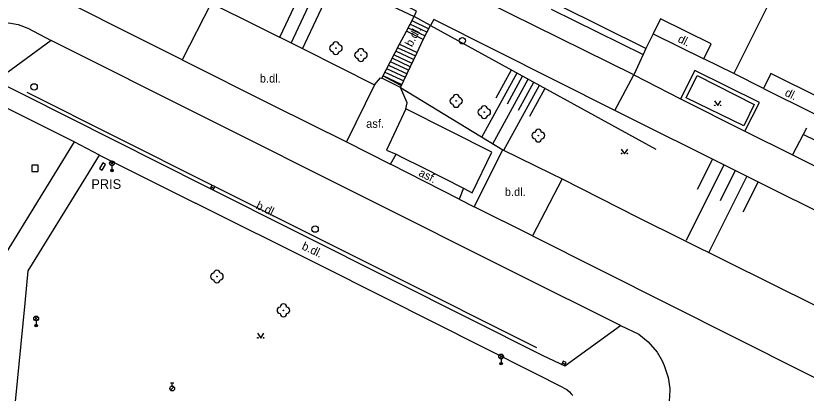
# Model space of a CAD drawing. Extents: x -602419 to -601554, y -1162937 to -1162362.
# Drawn here: x -602170.3 to -602108.3, y -1162597.4 to -1162567.9 of the extents above; entities that cross this region are included whole.
import ezdxf

# ---------------------------------------------------------------- set-up
doc = ezdxf.new("R2010")
doc.units = 0
doc.layers.add('Podklad', color=7, linetype='Continuous')

msp = doc.modelspace()

# ---------------------------------------------------------------- linework, layer by layer
at = {"layer": 'Podklad'}
for p, q in [((-602162.8625, -1162579.59), (-602162.5975, -1162579.325)), ((-602162.8625, -1162579.325), (-602162.5975, -1162579.59)), ((-602162.73, -1162579.645), (-602162.73, -1162580.02)), ((-602154.9636, -1162581.2978), (-602154.7364, -1162581.4022)), ((-602168.8025, -1162591.7299), (-602168.5375, -1162591.4649)), ((-602168.8025, -1162591.4649), (-602168.5375, -1162591.7299)), ((-602168.67, -1162591.7849), (-602168.67, -1162592.1599)), ((-602132.3825, -1162594.71), (-602132.1175, -1162594.445)), ((-602132.3825, -1162594.445), (-602132.1175, -1162594.71)), ((-602132.25, -1162594.765), (-602132.25, -1162595.14)), ((-602127.4436, -1162595.0678), (-602127.2164, -1162595.1722)), ((-602158.135, -1162596.6425), (-602157.885, -1162596.6425)), ((-602158.01, -1162596.8925), (-602158.01, -1162596.6425)), ((-602158.139, -1162597.216), (-602157.874, -1162596.951))]:
    msp.add_line(p, q, dxfattribs=at)
for points in [[(-602157.2199, -1162571.37), (-602207.76, -1162546.07)], [(-602139.07, -1162567.96), (-602138.87, -1162567.56), (-602144.3, -1162564.86), (-602155, -1162559.69)], [(-602155.35, -1162560.31), (-602139.07, -1162567.96)], [(-602108.54, -1162561.44), (-602114.03, -1162572.44)], [(-602121.85, -1162572.55), (-602137.35, -1162564.87), (-602140.48, -1162563.24), (-602142.89, -1162562.08)], [(-602149.59, -1162569.6), (-602147.06, -1162564.21)], [(-602148.7, -1162570.05), (-602146.15, -1162564.63)], [(-602147.8, -1162570.49), (-602145.25, -1162565.06)], [(-602154.95, -1162566.94), (-602157.2199, -1162571.37)], [(-602154.95, -1162566.94), (-602147.76, -1162570.51), (-602142.1599, -1162573.33)], [(-602120.9099, -1162570.48), (-602127.7, -1162567.12)], [(-602128.32, -1162567.4), (-602121.12, -1162570.94)], [(-602139.67, -1162569.12), (-602139.07, -1162567.96)], [(-602139.67, -1162569.12), (-602139.07, -1162567.96)], [(-602139.24, -1162568.29), (-602137.92, -1162568.94)], [(-602137.77, -1162568.67), (-602139.07, -1162567.96)], [(-602104.53, -1162584.69), (-602123.34, -1162575.32), (-602137.52, -1162568.21), (-602137.77, -1162568.67)], [(-602119.75, -1162568.15), (-602120.34, -1162569.33)], [(-602115.78, -1162570.12), (-602119.75, -1162568.15)], [(-602174.48, -1162570.34), (-602174.02, -1162569.73), (-602173.45, -1162569.23), (-602172.85, -1162568.87), (-602172.17, -1162568.62), (-602171.56, -1162568.49), (-602170.82, -1162568.48), (-602170.08, -1162568.61), (-602169.31, -1162568.89)], [(-602169.31, -1162568.89), (-602167.5, -1162569.84), (-602171.83, -1162573.01), (-602169.67, -1162574.07), (-602155.45, -1162581.23), (-602140.7199, -1162588.61), (-602128.9699, -1162594.49), (-602127.26, -1162595.32), (-602122.9, -1162592.1599), (-602121.46, -1162592.84)], [(-602139.53, -1162568.85), (-602138.21, -1162569.49)], [(-602138.06, -1162569.21), (-602139.39, -1162568.57)], [(-602138.36, -1162569.76), (-602137.77, -1162568.67)], [(-602138.36, -1162569.76), (-602137.77, -1162568.67)], [(-602137.77, -1162568.67), (-602120.13, -1162578.35)], [(-602140.2, -1162570.14), (-602139.67, -1162569.12)], [(-602140.2, -1162570.14), (-602139.67, -1162569.12)], [(-602138.36, -1162569.76), (-602139.67, -1162569.12)], [(-602120.34, -1162569.33), (-602120.9099, -1162570.48)], [(-602120.34, -1162569.33), (-602116.36, -1162571.29)], [(-602122.9, -1162592.1599), (-602131.127, -1162588.0499), (-602167.5, -1162569.84)], [(-602141.59, -1162572.81), (-602140.2, -1162570.14)], [(-602141.59, -1162572.81), (-602140.2, -1162570.14)], [(-602140.2, -1162570.14), (-602138.83, -1162570.78)], [(-602138.83, -1162570.78), (-602138.36, -1162569.76)], [(-602138.83, -1162570.78), (-602138.36, -1162569.76)], [(-602116.36, -1162571.29), (-602115.78, -1162570.12)], [(-602139.1, -1162571.34), (-602140.49, -1162570.69)], [(-602140.34, -1162570.42), (-602138.96, -1162571.06)], [(-602140.12, -1162573.54), (-602138.83, -1162570.78)], [(-602140.12, -1162573.54), (-602138.83, -1162570.78)], [(-602120.9099, -1162570.48), (-602121.12, -1162570.94)], [(-602157.2199, -1162571.37), (-602150.1599, -1162574.9099), (-602144.37, -1162577.79)], [(-602139.36, -1162571.9), (-602140.77, -1162571.24)], [(-602140.63, -1162570.9699), (-602139.23, -1162571.62)], [(-602121.12, -1162570.94), (-602121.85, -1162572.55)], [(-602114.03, -1162572.44), (-602116.36, -1162571.29)], [(-602139.75, -1162572.74), (-602141.2, -1162572.07)], [(-602141.06, -1162571.79), (-602139.62, -1162572.46)], [(-602139.49, -1162572.18), (-602140.92, -1162571.52)], [(-602140.01, -1162573.31), (-602141.49, -1162572.62)], [(-602141.4889, -1162572.6158), (-602140.12, -1162573.3399), (-602140.045, -1162573.3796)], [(-602141.35, -1162572.34), (-602139.88, -1162573.02)], [(-602133.75, -1162577.4099), (-602131, -1162572.39)], [(-602132.63, -1162574.33), (-602131.43, -1162572.15)], [(-602131.75, -1162574.81), (-602130.56, -1162572.63)], [(-602123.34, -1162575.32), (-602121.85, -1162572.55), (-602118.19, -1162574.42)], [(-602117.07, -1162572.19), (-602118.19, -1162574.42)], [(-602117.74, -1162574.33), (-602116.88, -1162572.58), (-602112.42, -1162574.86), (-602113.24, -1162576.54), (-602117.74, -1162574.33)], [(-602112.01, -1162574.69), (-602117.07, -1162572.19)], [(-602111.7, -1162573.6), (-602114.03, -1162572.44)], [(-602111.12, -1162572.43), (-602111.7, -1162573.6)], [(-602107.18, -1162574.38), (-602111.12, -1162572.43)], [(-602142.1599, -1162573.33), (-602141.7, -1162572.78), (-602141.59, -1162572.81)], [(-602140.12, -1162573.54), (-602141.59, -1162572.81)], [(-602132.89, -1162577.93), (-602130.12, -1162572.87)], [(-602130.88, -1162575.29), (-602129.68, -1162573.11)], [(-602169.4, -1162573.9), (-602155.24, -1162580.98), (-602141.25, -1162587.99), (-602129.48, -1162593.88)], [(-602142.1599, -1162573.33), (-602144.37, -1162577.79)], [(-602139.71, -1162575.21), (-602139.62, -1162574.74), (-602140.12, -1162573.54)], [(-602140.12, -1162573.54), (-602132.11, -1162578.4)], [(-602132.03, -1162578.44), (-602129.24, -1162573.35)], [(-602130, -1162575.77), (-602128.8, -1162573.59)], [(-602111.7, -1162573.6), (-602107.76, -1162575.56)], [(-602165.69, -1162577.79), (-602170.33, -1162575.46), (-602172.32, -1162574.48)], [(-602118.19, -1162574.42), (-602113.15, -1162576.94)], [(-602115.53, -1162574.575), (-602115.28, -1162574.95), (-602115.03, -1162574.575)], [(-602113.15, -1162576.94), (-602112.01, -1162574.69)], [(-602139.71, -1162575.21), (-602141.23, -1162578.43), (-602140.4699, -1162578.75)], [(-602135.19, -1162581.4099), (-602134.52, -1162581.78), (-602132.98, -1162578.58), (-602139.71, -1162575.21)], [(-602113.15, -1162576.94), (-602109.42, -1162578.8)], [(-602108.33, -1162576.71), (-602108.58, -1162577.2)], [(-602108.58, -1162577.2), (-602109.42, -1162578.8)], [(-602101.73, -1162580.55), (-602108.58, -1162577.2)], [(-602165.69, -1162577.79), (-602171.55, -1162587.26)], [(-602163.7199, -1162578.83), (-602165.69, -1162577.79)], [(-602144.37, -1162577.79), (-602140.9099, -1162579.53)], [(-602169.29, -1162587.88), (-602164.78, -1162580.56), (-602163.7199, -1162578.83)], [(-602163.7199, -1162578.83), (-602156.18, -1162582.58)], [(-602140.9099, -1162579.53), (-602140.4699, -1162578.75)], [(-602140.4699, -1162578.75), (-602140.03, -1162578.9699), (-602138.39, -1162579.79), (-602135.19, -1162581.4099)], [(-602134.35, -1162582.86), (-602132.11, -1162578.4)], [(-602132.11, -1162578.4), (-602128.33, -1162580.25), (-602127.46, -1162580.68)], [(-602122.83, -1162578.3449), (-602122.58, -1162578.7199), (-602122.33, -1162578.3449)], [(-602109.42, -1162578.8), (-602102.5, -1162582.23)], [(-602115.7, -1162579.13), (-602116.88, -1162581.5)], [(-602135.54, -1162582.26), (-602140.9099, -1162579.53)], [(-602114.8, -1162579.57), (-602117.76, -1162585.51)], [(-602113.9099, -1162580.02), (-602115.09, -1162582.39)], [(-602127.46, -1162580.68), (-602129.79, -1162585.13)], [(-602127.46, -1162580.68), (-602121.52, -1162583.69), (-602107.67, -1162590.57)], [(-602113.01, -1162580.46), (-602115.9699, -1162586.4099)], [(-602112.12, -1162580.9099), (-602113.3, -1162583.29)], [(-602135.19, -1162581.4099), (-602135.54, -1162582.26)], [(-602146.5, -1162587.4099), (-602156.18, -1162582.58)], [(-602135.54, -1162582.26), (-602134.35, -1162582.86)], [(-602129.79, -1162585.13), (-602134.35, -1162582.86)], [(-602129.79, -1162585.13), (-602076.67, -1162611.8)], [(-602127.37, -1162597.04), (-602129.68, -1162595.85), (-602141.45, -1162589.94), (-602146.5, -1162587.4099)], [(-602169.53, -1162590.4), (-602169.29, -1162587.88)], [(-602173.39, -1162629.19), (-602170.59, -1162601.27), (-602169.53, -1162590.4)], [(-602151.33, -1162592.765), (-602151.08, -1162593.14), (-602150.83, -1162592.765)], [(-602121.46, -1162592.84), (-602120.74, -1162593.43), (-602120.03, -1162594.24), (-602119.62, -1162594.92), (-602119.4699, -1162595.28), (-602119.1599, -1162596.23), (-602119.03, -1162597.08), (-602119.06, -1162597.75), (-602119.13, -1162598.4)], [(-602127.37, -1162597.04), (-602127.11, -1162597.17), (-602126.88, -1162597.35), (-602126.75, -1162597.49), (-602126.64, -1162597.63)]]:
    msp.add_lwpolyline(points, dxfattribs=at)
for points in [[(-602163.5002, -1162579.9888), (-602163.2449, -1162579.5589), (-602163.4598, -1162579.4312), (-602163.7151, -1162579.8611)], [(-602169.02, -1162580.11), (-602168.52, -1162580.11), (-602168.52, -1162579.61), (-602169.02, -1162579.61)], [(-602155.0158, -1162581.4114), (-602154.7886, -1162581.5158), (-602154.6842, -1162581.2886), (-602154.9114, -1162581.1842)], [(-602127.4958, -1162595.1814), (-602127.2686, -1162595.2858), (-602127.1642, -1162595.0586), (-602127.3914, -1162594.9542)]]:
    msp.add_lwpolyline(points, close=True, dxfattribs=at)
for centre, radius in [((-602135.29, -1162569.87), 0.25), ((-602145.19, -1162570.45), 0.025), ((-602143.23, -1162570.99), 0.025), ((-602168.83, -1162573.48), 0.25), ((-602135.77, -1162574.58), 0.025), ((-602115.5051, -1162574.9249), 0.025), ((-602115.0554, -1162574.9249), 0.025), ((-602133.57, -1162575.46), 0.025), ((-602129.33, -1162577.29), 0.025), ((-602122.8051, -1162578.6948), 0.025), ((-602122.3554, -1162578.6948), 0.025), ((-602162.73, -1162579.4575), 0.1875), ((-602162.73, -1162580.02), 0.1), ((-602162.73, -1162580.02), 0.0723), ((-602162.73, -1162580.02), 0.0438), ((-602146.82, -1162584.61), 0.25), ((-602154.51, -1162588.32), 0.025), ((-602149.3, -1162590.9699), 0.025), ((-602168.67, -1162591.5974), 0.1875), ((-602168.67, -1162592.1599), 0.1), ((-602168.67, -1162592.1599), 0.0723), ((-602168.67, -1162592.1599), 0.0438), ((-602151.3051, -1162593.1149), 0.025), ((-602150.8554, -1162593.1149), 0.025), ((-602132.25, -1162594.5775), 0.1875), ((-602132.25, -1162595.14), 0.1), ((-602132.25, -1162595.14), 0.0723), ((-602132.25, -1162595.14), 0.0438), ((-602158.01, -1162597.08), 0.1875)]:
    msp.add_circle(centre, radius, dxfattribs=at)
for centre, start, end in [((-602145.44, -1162570.45), 90, 270), ((-602145.19, -1162570.2), 0, 180), ((-602144.94, -1162570.45), 270, 90), ((-602145.19, -1162570.7), 180, 0), ((-602143.48, -1162570.99), 90, 270), ((-602143.23, -1162570.74), 0, 180), ((-602142.98, -1162570.99), 270, 90), ((-602143.23, -1162571.24), 180, 0), ((-602136.02, -1162574.58), 90, 270), ((-602135.77, -1162574.33), 0, 180), ((-602135.52, -1162574.58), 270, 90), ((-602135.77, -1162574.83), 180, 0), ((-602133.57, -1162575.21), 0, 180), ((-602133.82, -1162575.46), 90, 270), ((-602133.57, -1162575.71), 180, 0), ((-602133.32, -1162575.46), 270, 90), ((-602129.33, -1162577.04), 0, 180), ((-602129.58, -1162577.29), 90, 270), ((-602129.33, -1162577.54), 180, 0), ((-602129.08, -1162577.29), 270, 90), ((-602154.76, -1162588.32), 90, 270), ((-602154.51, -1162588.07), 0, 180), ((-602154.26, -1162588.32), 270, 90), ((-602154.51, -1162588.57), 180, 0), ((-602149.3, -1162590.7199), 0, 180), ((-602149.55, -1162590.9699), 90, 270), ((-602149.3, -1162591.2199), 180, 0), ((-602149.05, -1162590.9699), 270, 90)]:
    msp.add_arc(centre, 0.25, start, end, dxfattribs=at)

# ---------------------------------------------------------------- texts
for s, rotation, p in [('b.dl.', 62.16, (-602139.24, -1162570.4)), ('dl.', 333.82, (-602118.46, -1162569.94)), ('dl.', 333.82, (-602110.08, -1162574.14)), ('asf.', 333.39, (-602138.77, -1162580.4099)), ('b.dl.', 334.59, (-602151.5, -1162582.9699)), ('b.dl.', 334.59, (-602147.92, -1162586.1599))]:
    msp.add_text(s, height=0.65, rotation=rotation, dxfattribs=at).set_placement(p)
for s, height, p in [('b.dl.', 0.65, (-602151.15, -1162573.14)), ('asf.', 0.65, (-602142.82, -1162576.68)), ('PRIS', 0.75, (-602164.35, -1162581.46)), ('b.dl.', 0.65, (-602131.96, -1162582.02))]:
    msp.add_text(s, height=height, dxfattribs=at).set_placement(p)

doc.saveas('drawing.dxf')
